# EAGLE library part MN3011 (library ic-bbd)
3328-Stage BBD with 6 TAPS
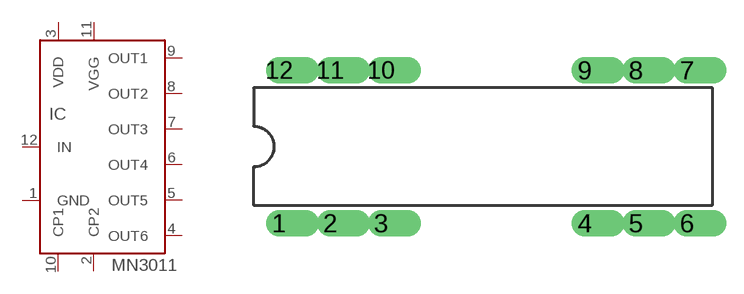
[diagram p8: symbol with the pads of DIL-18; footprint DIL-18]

Designator prefix IC

## MN3011  [DIL-18]
1  GND
2  CP2
3  VDD
4  OUT6
5  OUT5
6  OUT4
7  OUT3
8  OUT2
9  OUT1
10  CP1
11  VGG
12  IN

## Footprint DIL-18 (pad centres in mm)
Dual In Line Package
drill 0.813 offset: 1 -10.16,-3.81; 2 -7.62,-3.81; 3 -5.08,-3.81; 4 5.08,-3.81; 5 7.62,-3.81; 6 10.16,-3.81; 7 10.16,3.81; 8 7.62,3.81; 9 5.08,3.81; 10 -5.08,3.81; 11 -7.62,3.81; 12 -10.16,3.81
